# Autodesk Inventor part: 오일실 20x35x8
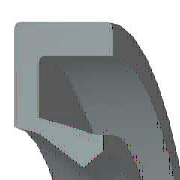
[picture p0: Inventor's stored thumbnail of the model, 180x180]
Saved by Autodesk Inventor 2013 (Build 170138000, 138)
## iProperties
IsCustomPart: 1
Created: 2012-02
Part Number: 오일실 20x35x8
Material: 고무
Description: 오일 실 - 비스프링, 조립 GA
Document SubType Name: Modeling
Standard: JIS B 2402
Designer: mdu-01
Standards Organization: JIS
Language: ko-KR
Size Designation: 20 35 8 A
Categories: <MemberInstance><Categories><Category DisplayName="샤프트 부품" InternalName="7f7aeb1f-a693-4053-b835-cee3144e0d98" Mnemonic="SHFT"><Category DisplayName="실링" Intern
Density: 0.93 g/cm^3
Author: mdu-01
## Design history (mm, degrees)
body "Solid1"
revolve "회전1" stored, may be unused: angle "d27" = 360 deg
fillet "모깎기1" dims "d28" = 0.4 (= 0.05 x b)
sketch "스케치2"
  geometry: L1 (12.464, -6)-(13.214, -8); L2 (11.464, -5.5)-(12.464, -6); L3 (10, -2.2)-(11.464, -5.5); L4 (11.154, -1.2)-(10, -2.2); L5 (14.5, -7)-(11.154, -1.2); L6 (14.5, -0.4)-(14.5, -7); L7 (16, -0.4)-(14.5, -0.4); L8 (16, 0)-(16, -0.4); L9 (17.5, 0)-(16, 0); L10 (17.5, -8)-(17.5, 0); L11 (13.214, -8)-(17.5, -8); L12 (0, -9.6)-(0, 1.6) reference; L13 (28, 0)-(14, 0) reference
  constraints: 22 end point, 3 horizontal, 3 vertical
  dimensions: "d2" = 8 distance of L10.start L9.start (= b); "d4" = 1.5 distance of L9.start L8.start (= 0.1 x dd - 0.1 x Diam); "d6" = 0.4 distance of L8.start L7.start (= 0.05 x b); "d8" = 1.15385 horizontal distance of L4.start L3.start (= 0.0769231 x dd - 0.0769231 x Diam); "d10" = 1 vertical distance of L5.start L10.start (= 0.125 x b); "d12" = 1.5 distance of L7.start L6.start (= 0.1 x dd - 0.1 x Diam); "d14" = 0.8 vertical distance of L4.start L6.start (= 0.1 x b); "d16" = 4.28571 distance of L1.end L10.start (= 0.285714 x dd - 0.285714 x Diam); "d18" = 0.75 horizontal distance of L1.start L1.end (= 0.05 x dd - 0.05 x Diam); "d20" = 1 vertical distance of L4.start L3.start (= 0.125 x b); "d22" = 2 vertical distance of L1.start L1.end (= 0.25 x b); "d24" = 1 horizontal distance of L2.start L1.start (= 0.0666667 x dd - 0.0666667 x Diam); "d26" = 0.5 vertical distance of L2.start L1.start (= 0.0625 x b); "d29" = 0 distance between parallel lines of L13 L9; "d30" = 10 distance from line of L3.start L12 (= 0.5 x Diam); "d31" = 17.5 distance between parallel lines of L12 L10 (= 0.5 x dd)
other parameters: "dd" = 35 [user parameter; used in 7 equation terms], "b" = 8 [user parameter; used in 8 equation terms], "d1" = 8 (derived), "d3" = 2 (derived), "d5" = 0.4 (derived), "d7" = 1.53846 (derived), "d9" = 1 (derived), "d11" = 2 (derived), "d13" = 0.8 (derived), "d15" = 5.71429 (derived), "d17" = 1 (derived), "d19" = 1 (derived), "d21" = 2 (derived), "d23" = 1.33333 (derived), "d25" = 0.5 (derived), "d32" = 0
